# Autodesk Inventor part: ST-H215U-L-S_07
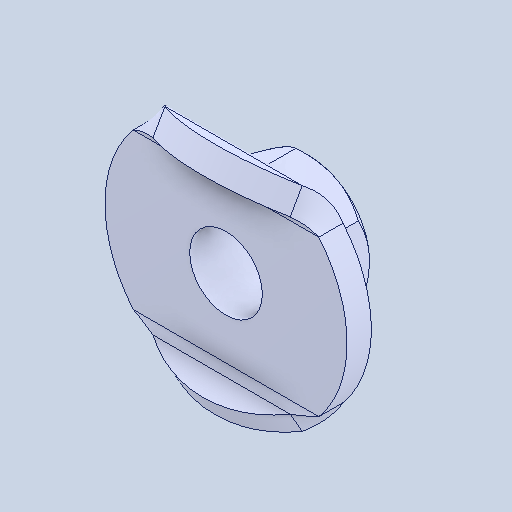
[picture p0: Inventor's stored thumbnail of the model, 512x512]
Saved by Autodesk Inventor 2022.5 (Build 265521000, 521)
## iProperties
Created: 2024-07
Part Number: ST-H215U-L-S_07
Material: 一般
Document SubType Name: Modeling
Designer: ImaoCorp
Density: 1 g/cm^3
Appearance: 既定
Author: ImaoCorp
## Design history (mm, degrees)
feature "ST-H215U-L-S_07"
node "ソリッド1"
